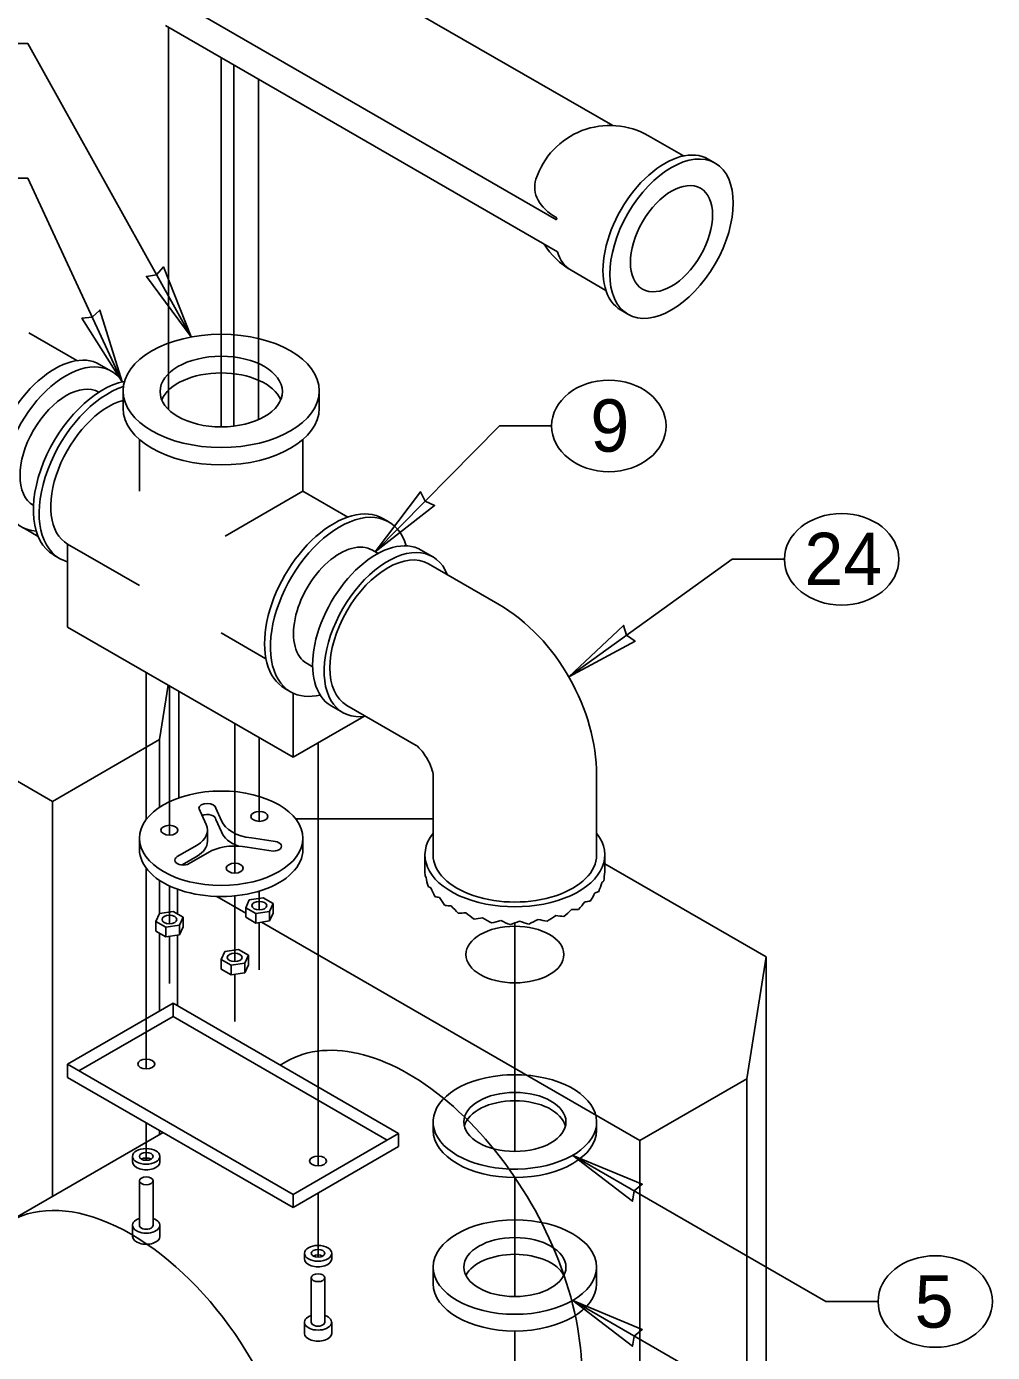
# Model space of a CAD drawing. Extents: x 99862 to 104211, y 98939 to 105076.
# Drawn here: x 102017.8 to 102313.3, y 101211.1 to 101616.6 of the extents above; entities that cross this region are included whole.
import ezdxf

# ---------------------------------------------------------------- set-up
doc = ezdxf.new("R2010")
doc.units = 0
for name, color, linetype in [('Level 11', 7, 'Continuous'), ('Level 12', 7, 'Continuous'), ('Level 15', 7, 'Continuous'), ('Level 20', 7, 'Continuous'), ('Level 26', 7, 'Continuous'), ('Level 4', 7, 'Continuous'), ('Level 5', 7, 'Continuous'), ('Level 6', 7, 'Continuous'), ('Level 7', 7, 'Continuous')]:
    doc.layers.add(name, color=color, linetype=linetype)

msp = doc.modelspace()

# ---------------------------------------------------------------- linework, layer by layer
at = {"layer": 'Level 11'}
for p, q in [((102070.55, 101377.54), (102072.77, 101372.57)), ((102077.53, 101373.72), (102075.76, 101377.54)), ((102077.53, 101370.32), (102075.76, 101374.13)), ((102052.4, 101368.39), (102052.4, 101364.99)), ((102073.16, 101367.44), (102073.16, 101370.84)), ((102093.24, 101367.44), (102086.63, 101368.46)), ((102102.4, 101364.99), (102102.4, 101368.39)), ((102070.09, 101366.29), (102063.96, 101362.76)), ((102067.64, 101360.63), (102074.57, 101364.63)), ((102085.33, 101365.66), (102093.24, 101364.44)), ((102070.09, 101362.89), (102065.43, 101360.21)), ((102084.88, 101347.12), (102086, 101349.53)), ((102084.88, 101344.21), (102084.88, 101347.12)), ((102087.95, 101345.35), (102084.88, 101347.12)), ((102086, 101349.53), (102090.19, 101350.18)), ((102090.19, 101350.18), (102093.25, 101348.41)), ((102093.25, 101348.41), (102092.13, 101346)), ((102093.25, 101345.5), (102093.25, 101348.41)), ((102057.37, 101342.91), (102058.49, 101345.33)), ((102057.37, 101340), (102057.37, 101342.91)), ((102060.43, 101341.15), (102057.37, 101342.91)), ((102058.49, 101345.33), (102062.68, 101345.98)), ((102062.68, 101345.98), (102065.74, 101344.21)), ((102065.74, 101344.21), (102064.62, 101341.79)), ((102065.74, 101341.3), (102065.74, 101344.21)), ((102084.88, 101344.21), (102087.95, 101342.44)), ((102092.13, 101346), (102087.95, 101345.35)), ((102087.95, 101342.44), (102087.95, 101345.35)), ((102087.95, 101342.44), (102092.13, 101343.09)), ((102092.13, 101343.09), (102092.13, 101346)), ((102092.13, 101343.09), (102093.25, 101345.5)), ((102057.37, 101340), (102060.43, 101338.24)), ((102064.62, 101341.79), (102060.43, 101341.15)), ((102060.43, 101338.24), (102060.43, 101341.15)), ((102060.43, 101338.24), (102064.62, 101338.88)), ((102064.62, 101338.88), (102064.62, 101341.79)), ((102064.62, 101338.88), (102065.74, 101341.3)), ((102077.36, 101331.3), (102078.48, 101333.72)), ((102077.36, 101328.39), (102077.36, 101331.3)), ((102080.42, 101329.54), (102077.36, 101331.3)), ((102078.48, 101333.72), (102082.66, 101334.37)), ((102082.66, 101334.37), (102085.73, 101332.6)), ((102085.73, 101332.6), (102084.61, 101330.18)), ((102085.73, 101329.69), (102085.73, 101332.6)), ((102077.36, 101328.39), (102080.42, 101326.63)), ((102084.61, 101330.18), (102080.42, 101329.54)), ((102080.42, 101326.63), (102080.42, 101329.54)), ((102080.42, 101326.63), (102084.61, 101327.27)), ((102084.61, 101327.27), (102084.61, 101330.18)), ((102084.61, 101327.27), (102085.73, 101329.69)), ((102142.22, 101281.63), (102142.22, 101279.08)), ((102192.22, 101279.08), (102192.22, 101281.63)), ((102050.3, 101271.09), (102050.3, 101269.39)), ((102058.63, 101269.39), (102058.63, 101271.09)), ((102052.38, 101263.63), (102052.38, 101250.03)), ((102056.55, 101250.03), (102056.55, 101263.63)), ((102050.3, 101250.03), (102050.3, 101246.62)), ((102058.63, 101246.62), (102058.63, 101250.03)), ((102102.85, 101241.45), (102102.85, 101239.75)), ((102111.19, 101239.75), (102111.19, 101241.45)), ((102104.94, 101233.99), (102104.94, 101220.38)), ((102109.1, 101220.38), (102109.1, 101233.99)), ((102142.22, 101237.24), (102142.22, 101232.13)), ((102192.22, 101232.13), (102192.22, 101237.24)), ((102102.85, 101220.38), (102102.85, 101216.98)), ((102111.19, 101216.98), (102111.19, 101220.38))]:
    msp.add_line(p, q, dxfattribs=at)
for centre, major_axis in [((102077.4, 101368.39), (-25, 0)), ((102089.07, 101375.04), (-2.6, 0)), ((102061.56, 101370.84), (-2.6, 0)), ((102081.54, 101359.23), (-2.6, 0)), ((102089.07, 101347.77), (2.27, 0)), ((102061.56, 101343.56), (2.27, 0)), ((102081.54, 101331.95), (2.27, 0)), ((102167.22, 101281.63), (-15.62, 0)), ((102054.46, 101271.09), (-4.17, 0)), ((102054.46, 101271.09), (-2.08, 0)), ((102054.46, 101263.63), (-2.08, 0)), ((102167.22, 101237.24), (-15.62, 0)), ((102107.02, 101241.45), (-4.17, 0)), ((102107.02, 101241.45), (-2.08, 0)), ((102107.02, 101233.99), (-2.08, 0))]:
    msp.add_ellipse(centre, major_axis=major_axis, ratio=0.57735, dxfattribs=at)
for centre, major_axis, start_param, end_param in [((102073.15, 101377.54), (-2.6, 0), 3.141593, 6.283185), ((102073.15, 101374.13), (-2.6, 0), 3.141593, 5.379094), ((102061.56, 101370.84), (-11.61, 0), 2.396309, 3.403392), ((102089, 101375.08), (-11.71, 0), 0.203445, 1.367352), ((102061.56, 101367.44), (-11.61, 0), 2.396309, 3.141593), ((102089, 101371.68), (-11.71, 0), 0.203445, 1.005854), ((102093.24, 101365.94), (-2.6, 0), 1.570796, 4.712389), ((102077.4, 101364.99), (-25, 0), 6.283185, 9.424778), ((102081.64, 101359.24), (-11.71, 0), 4.392235, 5.361438), ((102065.8, 101361.69), (-2.6, 0), 5.497787, 8.63938), ((102167.22, 101281.63), (-25, 0), 4.514208, 4.979655), ((102167.22, 101279.08), (15.62, 0), 0.141897, 2.999696), ((102167.22, 101279.08), (25, 0), 3.141593, 6.283185), ((102054.46, 101269.39), (-2.08, 0), 3.926991, 5.497787), ((102054.46, 101269.39), (-4.17, 0), 0, 3.141593), ((102054.46, 101250.03), (-4.17, 0), 5.235988, 10.471976), ((102054.46, 101250.03), (-2.08, 0), 0, 3.141593), ((102054.46, 101246.62), (-4.17, 0), 6.283185, 9.424778), ((102107.02, 101239.75), (-4.17, 0), 0, 3.141593), ((102107.02, 101239.75), (-2.08, 0), 3.926991, 5.497787), ((102167.22, 101232.13), (15.62, 0), 0.286757, 2.854836), ((102167.22, 101232.13), (25, 0), 3.141593, 6.283185), ((102107.02, 101220.38), (-4.17, 0), 5.235988, 10.471976), ((102107.02, 101220.38), (-2.08, 0), 0, 3.141593), ((102107.02, 101216.98), (-4.17, 0), 6.283185, 9.424778)]:
    msp.add_ellipse(centre, major_axis=major_axis, ratio=0.57735, start_param=start_param, end_param=end_param, dxfattribs=at)
at = {"layer": 'Level 12'}
for p, q in [((102197.14, 101586.33), (102095.17, 101645.2)), ((102179.92, 101557.53), (102060.37, 101626.55)), ((102060.37, 101616.87), (102180.23, 101547.66)), ((102218.79, 101577.01), (102208.12, 101583.16)), ((102228.48, 101574.84), (102226.38, 101576.05)), ((102184.4, 101542.08), (102195.06, 101535.92)), ((102199.69, 101529.82), (102201.79, 101528.61))]:
    msp.add_line(p, q, dxfattribs=at)
for start, end in [(60, 162.1705), (212.1144, 240)]:
    msp.add_arc((102196.26, 101562.62), 23.72, start, end, dxfattribs=at)
for centre, major_axis, start_param, end_param in [((102213.04, 101552.94), (13.34, 23.11), 0, 3.141593), ((102196.26, 101567.46), (-22.97, 0), 6.099581, 7.068583), ((102196.26, 101562.62), (11.86, 20.54), 2.103514, 2.129786), ((102196.26, 101562.62), (11.86, 20.54), 2.654898, 3.141593)]:
    msp.add_ellipse(centre, major_axis=major_axis, ratio=0.57735, start_param=start_param, end_param=end_param, dxfattribs=at)
for major_axis in [(13.34, 23.11), (-8.9, -15.41)]:
    msp.add_ellipse((102215.13, 101551.72), major_axis=major_axis, ratio=0.57735, dxfattribs=at)
at = {"layer": 'Level 15'}
for p, q in [((102061.3, 101499.45), (102061.3, 101616.33)), ((102002.26, 101611.44), (102018.26, 101611.44)), ((102068.22, 101521.67), (102018.26, 101611.44)), ((102077.4, 101494.14), (102077.4, 101607.04)), ((102081.29, 101494.39), (102081.29, 101604.79)), ((102088.81, 101496.4), (102088.81, 101600.45)), ((102002.26, 101570.18), (102018.26, 101570.18)), ((102047.13, 101507.93), (102018.26, 101570.18)), ((102124.5, 101455.95), (102162.47, 101494.46)), ((102178.47, 101494.46), (102162.47, 101494.46)), ((102183.7, 101417.71), (102233.66, 101453.67)), ((102249.66, 101453.67), (102233.66, 101453.67)), ((102054.46, 101374.14), (102054.46, 101419.06)), ((102061.56, 101369.34), (102061.56, 101414.96)), ((102081.54, 101357.72), (102081.54, 101403.42)), ((102089, 101373.54), (102089, 101399.12)), ((102107.02, 101268.17), (102107.02, 101397.55)), ((102054.46, 101297.82), (102054.46, 101359.24)), ((102061.56, 101342.25), (102061.56, 101353.82)), ((102089, 101346.46), (102089, 101352.2)), ((102081.54, 101330.64), (102081.54, 101350.75)), ((102089, 101328.19), (102089, 101342.6)), ((102167.23, 101272.61), (102167.23, 101342.48)), ((102061.56, 101323.98), (102061.56, 101338.41)), ((102081.54, 101312.37), (102081.54, 101326.8)), ((102054.46, 101269.89), (102054.46, 101281.37)), ((102184.9, 101271.4), (102262.3, 101226.71)), ((102167.23, 101228.22), (102167.23, 101264.65)), ((102107.02, 101240.24), (102107.02, 101259.87)), ((102184.9, 101227.03), (102262.3, 101182.34)), ((102278.3, 101226.71), (102262.3, 101226.71)), ((102167.23, 101201.93), (102167.23, 101217.7))]:
    msp.add_line(p, q, dxfattribs=at)
for points in [[(102068.22, 101521.67), (102054.51, 101540.16), (102057.63, 101540.69), (102059.73, 101543.07)], [(102047.13, 101507.93), (102034.82, 101527.38), (102037.97, 101527.68), (102040.24, 101529.9)], [(102124.5, 101455.95), (102142.65, 101470.11), (102139.79, 101471.46), (102138.4, 101474.31)], [(102183.7, 101417.71), (102203.97, 101428.62), (102201.37, 101430.43), (102200.49, 101433.47)], [(102184.9, 101271.4), (102206.16, 101262.57), (102203.75, 101260.51), (102203.18, 101257.39)], [(102184.9, 101227.03), (102206.16, 101218.2), (102203.75, 101216.15), (102203.18, 101213.03)]]:
    msp.add_lwpolyline(points, close=True, dxfattribs=at)
at = {"layer": 'Level 20'}
for p, q in [((102018.51, 101522.92), (102033.24, 101514.42)), ((102125.36, 101455.46), (102123.64, 101456.45)), ((102162.04, 101440.05), (102140.83, 101452.3)), ((102103.64, 101421.81), (102105.36, 101420.82)), ((102115.83, 101409), (102137.04, 101396.75)), ((102142.22, 101387.78), (102142.22, 101363.29)), ((102192.22, 101363.29), (102192.22, 101387.78)), ((102139.72, 101363.29), (102139.72, 101358.35)), ((102194.72, 101358.35), (102194.72, 101363.29))]:
    msp.add_line(p, q, dxfattribs=at)
for centre, major_axis, ratio, start_param, end_param in [((102030, 101487.42), (13.75, 23.82), 0.57735, 5.990419, 9.717544), ((102030, 101487.42), (-10, -17.32), 0.57735, 3.143881, 6.280897), ((102124.79, 101432.69), (13.75, 23.82), 0.57735, 0, 3.141593), ((102113.64, 101439.13), (10, 17.32), 0.57735, 0, 3.141593), ((102167.22, 101358.89), (-27.03, -5.37), 0.947565, 6.097095, 6.149455), ((102167.22, 101358.89), (-27.5, -1.68), 0.206802, 0.039705, 0.144424), ((102167.22, 101358.89), (25.29, -11.7), 0.922162, 3.702024, 3.806744), ((102167.22, 101358.89), (27.49, -2.79), 0.213589, 6.04308, 6.1478), ((102167.22, 101358.89), (-27.03, -5.37), 0.947565, 2.798423, 2.903143), ((102167.22, 101358.89), (-27.49, -3.89), 0.223561, 0.230203, 0.334923), ((102167.22, 101358.89), (24.12, -15.48), 0.853385, 4.009326, 4.114045), ((102167.22, 101358.89), (-24.14, -16.11), 0.818147, 2.06586, 2.17058), ((102167.22, 101358.89), (27.48, -4.96), 0.236491, 5.854579, 5.959298), ((102167.22, 101358.89), (-24.4, -14.28), 0.888613, 2.295514, 2.400234), ((102167.22, 101358.89), (-27.46, -6), 0.252109, 0.416228, 0.520948), ((102167.22, 101358.89), (24.3, -16.43), 0.783391, 4.204501, 4.309221), ((102167.22, 101358.89), (-27.4, -7.98), 0.290225, 0.596374, 0.701094), ((102167.22, 101358.89), (24.82, -16.54), 0.715795, 4.372134, 4.476854), ((102167.22, 101358.89), (-24.54, -16.55), 0.749264, 1.888318, 1.993037), ((102167.22, 101358.89), (27.43, -7.01), 0.270119, 5.671382, 5.776101), ((102167.22, 101358.89), (-27.3, -9.8), 0.335596, 0.770216, 0.874936), ((102167.22, 101358.89), (25.39, -16.22), 0.650745, 4.530376, 4.635096), ((102167.22, 101358.89), (-27.14, -11.45), 0.386234, 0.938087, 1.042807), ((102167.22, 101358.89), (25.93, -15.58), 0.588004, 4.685558, 4.790278), ((102167.22, 101358.89), (-26.91, -12.9), 0.440657, 1.100807, 1.205527), ((102167.22, 101358.89), (26.39, -14.68), 0.527399, 4.840753, 4.945473), ((102167.22, 101358.89), (-26.58, -14.14), 0.497899, 1.259485, 1.364205), ((102167.22, 101358.89), (26.76, -13.55), 0.468967, 4.997892, 5.102266), ((102167.22, 101358.89), (-26.18, -15.07), 0.558157, 1.416585, 1.52165), ((102167.22, 101358.89), (27.04, -12.13), 0.414287, 5.15799, 5.263055), ((102167.22, 101358.89), (-25.67, -15.94), 0.6191, 1.570694, 1.675068), ((102167.22, 101358.89), (27.23, -10.65), 0.360362, 5.323611, 5.42833), ((102167.22, 101358.89), (-25.11, -16.43), 0.682966, 1.726553, 1.831273), ((102167.22, 101358.89), (27.36, -8.91), 0.312139, 5.494389, 5.599109)]:
    msp.add_ellipse(centre, major_axis=major_axis, ratio=ratio, start_param=start_param, end_param=end_param, dxfattribs=at)
for centre in [(102195.97, 101494.46), (102267.16, 101453.67), (102295.8, 101226.71)]:
    msp.add_ellipse(centre, major_axis=(-17.5, 0), ratio=0.8, dxfattribs=at)
for points in [[(102192.22, 101387.78), (102192.22, 101397.48), (102186.18, 101418.45), (102171.22, 101434.75), (102162.04, 101440.05)], [(102137.04, 101396.75), (102136.9, 101396.84), (102138.37, 101395.97), (102141.33, 101391.37), (102142.26, 101388.1), (102142.22, 101387.68), (102142.22, 101387.78)]]:
    msp.add_open_spline(points, degree=3, dxfattribs=at)
at = {"layer": 'Level 26'}
for p, q in [((101884.33, 101461.28), (102025.75, 101379.63)), ((102021.4, 101460.66), (102016.88, 101463.27)), ((102058.52, 101398.55), (102061.14, 101415.2)), ((102064.39, 101413.32), (102064.39, 101380.72)), ((102025.75, 101379.63), (102058.52, 101398.55)), ((102058.52, 101398.55), (102058.52, 101377.85)), ((102025.75, 101379.63), (102025.75, 101258.79)), ((102142.22, 101374.33), (102100.18, 101374.33)), ((102244.04, 101332.12), (102194.72, 101360.59)), ((102058.52, 101355.53), (102058.52, 101345.33)), ((102063.98, 101345.23), (102063.98, 101352.81)), ((102076.07, 101350.57), (102084.88, 101345.49)), ((102058.52, 101339.34), (102058.52, 101315.47)), ((102063.98, 101317.17), (102063.98, 101338.78)), ((102089.69, 101342.71), (102205.4, 101275.91)), ((102238.16, 101294.83), (102244.04, 101332.12)), ((102244.04, 101332.12), (102244.04, 101182.83)), ((102097.19, 101300.04), (102095.42, 101299.02)), ((102205.4, 101275.91), (102238.16, 101294.83)), ((102238.16, 101294.83), (102238.16, 101140.84)), ((102059.66, 101278.37), (102012.33, 101251.05)), ((102058.52, 101279.03), (102058.52, 101277.71)), ((102205.4, 101275.91), (102205.4, 101114.35))]:
    msp.add_line(p, q, dxfattribs=at)
msp.add_ellipse((102167.22, 101332.82), major_axis=(15, 0), ratio=0.57735, dxfattribs=at)
for centre, start_param, end_param in [((102134.69, 101235.08), 0, 3.141593), ((102049.83, 101186.09), 5.909304, 11.369456)]:
    msp.add_ellipse(centre, major_axis=(37.5, -64.95), ratio=0.57735, start_param=start_param, end_param=end_param, dxfattribs=at)
at = {"layer": 'Level 4'}
msp.add_ellipse((102167.22, 101237.24), major_axis=(-25, 0), ratio=0.57735, dxfattribs=at)
at = {"layer": 'Level 5'}
msp.add_ellipse((102167.22, 101281.63), major_axis=(-25, 0), ratio=0.57735, start_param=4.979655, end_param=10.797393, dxfattribs=at)
at = {"layer": 'Level 6'}
for p, q in [((102047.4, 101505.18), (102047.4, 101504.19)), ((102107.4, 101499.86), (102107.4, 101505.18)), ((102047.4, 101504.19), (102047.4, 101499.86)), ((102052.4, 101490.28), (102052.4, 101474.49)), ((102102.4, 101474.49), (102102.4, 101490.28)), ((102102.4, 101474.49), (102078.58, 101460.73)), ((102116.08, 101466.59), (102102.4, 101474.49)), ((102128.64, 101465.11), (102126.87, 101466.13)), ((102030.43, 101458.3), (102052.4, 101445.62)), ((102030.43, 101458.3), (102030.43, 101432.93)), ((102026.16, 101454.99), (102027.93, 101453.97)), ((102030.43, 101432.93), (102099.37, 101393.13)), ((102077.4, 101431.19), (102091.08, 101423.29)), ((102096.87, 101414.17), (102098.64, 101413.15)), ((102099.37, 101412.77), (102099.37, 101393.13)), ((102121, 101405.62), (102099.37, 101393.13)), ((102062.72, 101317.9), (102030.43, 101299.25)), ((102062.72, 101317.9), (102131.66, 101278.09)), ((102062.72, 101317.9), (102062.72, 101313.9)), ((102062.72, 101313.9), (102033.89, 101297.25)), ((102062.72, 101313.9), (102128.2, 101276.09)), ((102030.43, 101299.25), (102099.37, 101259.45)), ((102030.43, 101299.25), (102030.43, 101295.25)), ((102030.43, 101295.25), (102099.37, 101255.45)), ((102131.66, 101278.09), (102099.37, 101259.45)), ((102131.66, 101278.09), (102131.66, 101274.09)), ((102131.66, 101274.09), (102099.37, 101255.45)), ((102099.37, 101259.45), (102099.37, 101255.45))]:
    msp.add_line(p, q, dxfattribs=at)
for centre, major_axis, start_param, end_param in [((102077.4, 101505.18), (30, 0), 0.000426, 6.283185), ((102077.4, 101504.96), (18.71, 0), 0.000426, 6.283185), ((102077.4, 101499.86), (-18.75, 0), 3.384387, 6.040391), ((102041.16, 101480.98), (15, 25.98), 0.470604, 3.141593), ((102042.93, 101479.95), (15, 25.98), 0.566145, 3.141593), ((102042.93, 101479.95), (12.5, 21.65), 0.529676, 3.141593), ((102077.4, 101499.86), (30, 0), 3.141593, 6.283185), ((102111.87, 101440.15), (15, 25.98), 0, 3.141593), ((102113.64, 101439.13), (15, 25.98), 5.783351, 9.424778), ((102042.93, 101479.95), (15, 25.98), 3.141593, 3.296854), ((102113.64, 101439.13), (15, 25.98), 3.141593, 3.641427)]:
    msp.add_ellipse(centre, major_axis=major_axis, ratio=0.57735, start_param=start_param, end_param=end_param, dxfattribs=at)
for centre in [(102054.46, 101299.32), (102107.02, 101269.68)]:
    msp.add_ellipse(centre, major_axis=(-2.6, 0), ratio=0.57735, dxfattribs=at)
at = {"layer": 'Level 7'}
for p, q in [((102043.75, 101511.23), (102040.22, 101513.27)), ((102142.08, 101454.46), (102138.54, 101456.5)), ((102111.04, 101408.87), (102114.58, 101406.83))]:
    msp.add_line(p, q, dxfattribs=at)
for centre, major_axis, ratio, start_param, end_param in [((102026.47, 101489.46), (13.75, 23.82), 0.57735, 0, 3.141593), ((102128.33, 101430.65), (13.75, 23.82), 0.57735, 5.853486, 9.854478), ((102128.33, 101430.65), (-12.5, -21.65), 0.57735, 3.141593, 6.283185), ((102167.22, 101363.29), (-27.5, 0), 0.57735, 5.853486, 9.854478), ((102167.22, 101363.29), (-25, 0), 0.57735, 0, 3.141593), ((102167.22, 101358.89), (27.5, -0.56), 0.203365, 6.234982, 6.287342)]:
    msp.add_ellipse(centre, major_axis=major_axis, ratio=ratio, start_param=start_param, end_param=end_param, dxfattribs=at)

# ---------------------------------------------------------------- texts
at = {"layer": 'Level 20'}
for s, p in [('9', (102190.32, 101486.59)), ('24', (102255.77, 101445.8)), ('5', (102289.49, 101218.71))]:
    msp.add_text(s, height=16, dxfattribs=at).set_placement(p)

doc.saveas('drawing.dxf')
